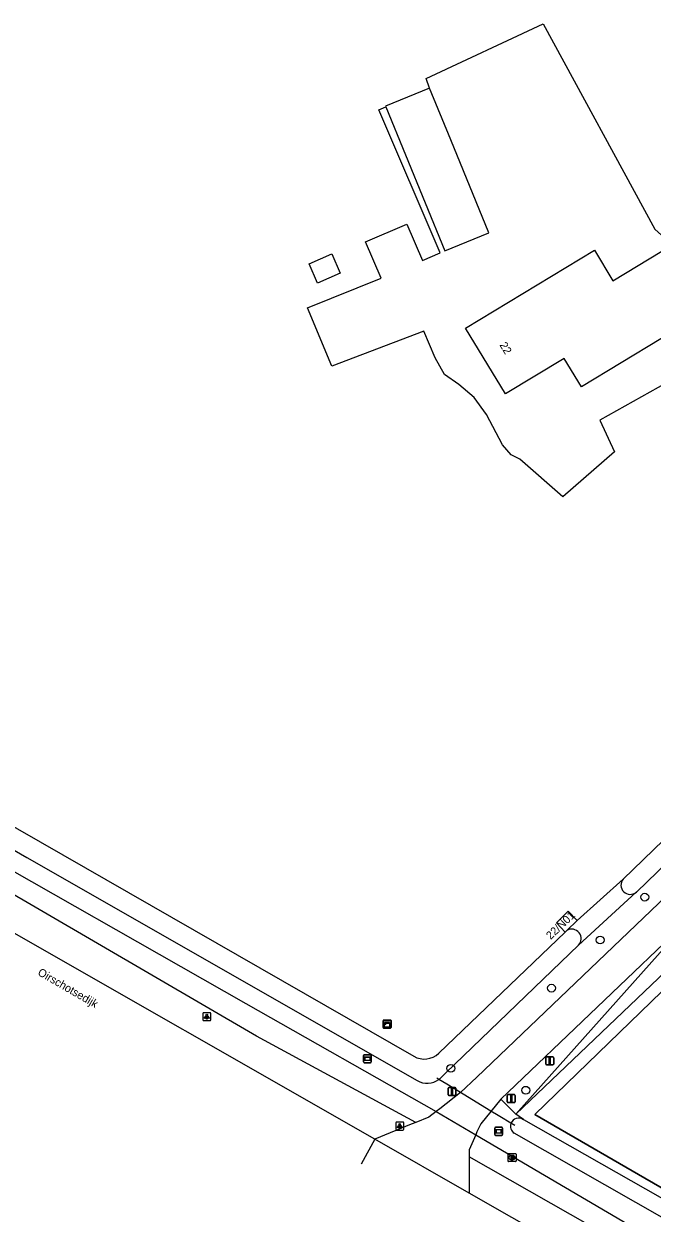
# Model space of a CAD drawing. Extents: x 157154 to 159278, y 385000 to 386650.
# Drawn here: x 157381.9 to 157460.3, y 385928.5 to 386077 of the extents above; entities that cross this region are included whole.
import ezdxf

# ---------------------------------------------------------------- set-up
doc = ezdxf.new("R2010")
doc.units = 0
for name, color, linetype in [('IMGEO_Berm_groen', 7, 'Continuous'), ('IMGEO_Boom', 7, 'Continuous'), ('IMGEO_Brandkraan', 7, 'Continuous'), ('IMGEO_Duiker', 7, 'Continuous'), ('IMGEO_Gemengd_bos', 7, 'Continuous'), ('IMGEO_Groenvoorziening', 7, 'Continuous'), ('IMGEO_Hek', 7, 'Continuous'), ('IMGEO_Kast', 7, 'Continuous'), ('IMGEO_Lichtpunt', 7, 'Continuous'), ('IMGEO_Loofbos', 7, 'Continuous'), ('IMGEO_Openbare_ruimte_label', 7, 'Continuous'), ('IMGEO_Pand', 7, 'Continuous'), ('IMGEO_Pand_nummerreeks', 7, 'Continuous'), ('IMGEO_Rijbaan_lokaal_gesloten', 7, 'Continuous'), ('IMGEO_Rijbaan_lokaal_open', 7, 'Continuous'), ('IMGEO_Verkeersbordpaal', 7, 'Continuous'), ('IMGEO_Verklikker', 7, 'Continuous'), ('IMGEO_Voetpad_open', 7, 'Continuous'), ('IMGEO_Waterloop', 7, 'Continuous')]:
    doc.layers.add(name, color=color, linetype=linetype)

msp = doc.modelspace()

# ---------------------------------------------------------------- linework, layer by layer
at = {"layer": 'IMGEO_Berm_groen'}
for points in [[(157441.44, 385942.69), (157443.32, 385940.84)], [(157444.27, 385940.14), (157443.32, 385940.84)]]:
    msp.add_lwpolyline(points, dxfattribs=at)
at = {"layer": 'IMGEO_Boom'}
for centre in [(157459.42, 385967.94), (157453.84, 385962.58), (157447.77, 385956.57), (157435.2, 385946.55), (157444.56, 385943.81)]:
    msp.add_circle(centre, 0.489, dxfattribs=at)
at = {"layer": 'IMGEO_Brandkraan'}
for p, q in [((157442.34, 385934.97), (157442.34, 385935.83)), ((157442.41, 385935.9), (157443.26, 385935.9)), ((157442.82, 385935.68), (157442.85, 385935.68)), ((157443.34, 385935.83), (157443.34, 385934.97)), ((157443.26, 385934.9), (157442.41, 385934.9)), ((157442.85, 385935.12), (157442.82, 385935.12))]:
    msp.add_line(p, q, dxfattribs=at)
for points in [[(157442.34, 385934.97), (157442.34, 385935.83)], [(157442.41, 385935.9), (157443.26, 385935.9)], [(157443.34, 385935.83), (157443.34, 385934.97)], [(157443.26, 385934.9), (157442.41, 385934.9)], [(157442.68, 385935.6), (157442.68, 385935.2), (157442.9, 385935.2)], [(157442.91, 385935.6), (157442.68, 385935.6)], [(157442.86, 385935.52), (157442.81, 385935.52), (157442.81, 385935.44)], [(157442.81, 385935.44), (157442.86, 385935.44)], [(157442.87, 385935.37), (157442.81, 385935.37), (157442.81, 385935.29)], [(157442.81, 385935.29), (157442.87, 385935.29)]]:
    msp.add_lwpolyline(points, dxfattribs=at)
for centre, radius, start, end in [((157442.41, 385935.82), 0.0765, 91.552, 178.448), ((157442.41, 385935.82), 0.0765, 91.552, 178.448), ((157443.26, 385935.82), 0.0765, 1.552, 88.448), ((157443.26, 385935.82), 0.0765, 1.552, 88.448), ((157442.41, 385934.98), 0.0765, 181.552, 268.448), ((157442.41, 385934.98), 0.0765, 181.552, 268.448), ((157442.86, 385935.48), 0.0379, 267.8285, 90.9355), ((157442.87, 385935.33), 0.0404, 269.8759, 90.5077), ((157442.9, 385935.45), 0.251, 268.6676, 293.5347), ((157442.92, 385935.45), 0.145, 59.4692, 91.5367), ((157442.94, 385935.5), 0.0922, 285.5137, 58.1501), ((157442.95, 385935.31), 0.105, 301.3115, 78.989), ((157443.26, 385934.98), 0.0765, 271.552, 358.448), ((157443.26, 385934.98), 0.0765, 271.552, 358.448)]:
    msp.add_arc(centre, radius, start, end, dxfattribs=at)
for centre, major_axis, ratio, start_param, end_param in [((157442.82, 385935.4), (-0.387, 0.002), 0.722429, 4.712389, 7.853982), ((157442.85, 385935.4), (-0.39, 0.002), 0.717154, 1.570796, 4.712389)]:
    msp.add_ellipse(centre, major_axis=major_axis, ratio=ratio, start_param=start_param, end_param=end_param, dxfattribs=at)
at = {"layer": 'IMGEO_Duiker'}
msp.add_lwpolyline([(157443.18, 385939.39), (157442.7, 385939.68), (157441.3, 385940.54), (157439.99, 385941.34), (157436.4, 385943.52), (157434.69, 385944.57), (157433.71, 385945.17), (157433.47, 385945.31)], dxfattribs=at)
at = {"layer": 'IMGEO_Gemengd_bos'}
for points in [[(157539.91, 385944.1), (157541.98, 385942.04), (157512.6, 385902.07), (157445.67, 385940.77), (157469.45, 385963.81), (157474.9, 385958.09), (157475.08, 385958.27), (157469.44, 385964.19), (157468.14, 385962.94), (157468, 385963.08), (157467.36, 385963.75)], [(157467.36, 385963.75), (157443.32, 385940.84)]]:
    msp.add_lwpolyline(points, dxfattribs=at)
at = {"layer": 'IMGEO_Groenvoorziening'}
for points in [[(157458.36, 385968.55), (157451.13, 385961.92)], [(157443.32, 385940.84), (157465.49, 385965.68)]]:
    msp.add_lwpolyline(points, dxfattribs=at)
at = {"layer": 'IMGEO_Hek'}
msp.add_lwpolyline([(157475.08, 385958.27), (157474.9, 385958.09), (157469.45, 385963.81), (157445.67, 385940.77), (157512.6, 385902.07), (157541.98, 385942.04), (157539.91, 385944.1)], dxfattribs=at)
at = {"layer": 'IMGEO_Kast'}
for p, q in [((157426.74, 385951.65), (157426.74, 385952.5)), ((157426.74, 385952.5), (157426.74, 385951.65)), ((157426.81, 385952.58), (157427.65, 385952.58)), ((157427.65, 385952.58), (157426.81, 385952.58)), ((157427.73, 385952.51), (157427.73, 385951.66)), ((157427.73, 385951.66), (157427.73, 385952.51)), ((157427.66, 385951.58), (157426.82, 385951.58)), ((157426.82, 385951.58), (157427.66, 385951.58))]:
    msp.add_line(p, q, dxfattribs=at)
for points in [[(157426.93, 385952.37), (157427.53, 385952.37), (157427.53, 385952.28), (157426.93, 385952.28), (157426.93, 385952.37)], [(157426.93, 385952.2), (157427.53, 385952.2), (157427.53, 385951.71), (157426.93, 385951.71), (157426.93, 385952.2)]]:
    msp.add_lwpolyline(points, dxfattribs=at)
msp.add_circle((157427.01, 385952.04), 0.0377, dxfattribs=at)
for centre, start, end in [((157426.81, 385952.5), 92.4484, 184.2845), ((157426.81, 385952.5), 92.4484, 184.2845), ((157427.66, 385952.5), 2.4484, 94.2845), ((157427.66, 385952.5), 2.4484, 94.2845), ((157426.81, 385951.66), 182.4484, 274.2845), ((157426.81, 385951.66), 182.4484, 274.2845), ((157427.66, 385951.66), 272.4484, 4.2845), ((157427.66, 385951.66), 272.4484, 4.2845)]:
    msp.add_arc(centre, 0.0779, start, end, dxfattribs=at)
at = {"layer": 'IMGEO_Lichtpunt'}
for p, q in [((157405.13, 385953.5), (157404.32, 385953.5)), ((157405.13, 385953.5), (157404.32, 385953.5)), ((157404.22, 385953.41), (157404.22, 385952.6)), ((157404.22, 385953.41), (157404.22, 385952.6)), ((157404.32, 385952.51), (157405.13, 385952.51)), ((157404.32, 385952.51), (157405.13, 385952.51)), ((157405.22, 385952.6), (157405.22, 385953.41)), ((157405.22, 385952.6), (157405.22, 385953.41)), ((157428.32, 385939.75), (157428.32, 385938.94)), ((157428.32, 385939.75), (157428.32, 385938.94)), ((157429.22, 385939.84), (157428.42, 385939.84)), ((157429.22, 385939.84), (157428.42, 385939.84)), ((157428.42, 385938.84), (157429.22, 385938.84)), ((157428.42, 385938.84), (157429.22, 385938.84)), ((157429.32, 385938.94), (157429.32, 385939.75)), ((157429.32, 385938.94), (157429.32, 385939.75))]:
    msp.add_line(p, q, dxfattribs=at)
for points in [[(157404.6, 385953.07), (157404.64, 385953.05), (157404.45, 385952.78), (157404.41, 385952.81), (157404.6, 385953.07)], [(157404.7, 385953.03), (157404.75, 385953.03), (157404.75, 385952.7), (157404.7, 385952.7), (157404.7, 385953.03)], [(157404.81, 385953.05), (157404.85, 385953.07), (157405.03, 385952.81), (157405, 385952.78), (157404.81, 385953.05)], [(157428.7, 385939.41), (157428.73, 385939.38), (157428.55, 385939.12), (157428.51, 385939.15), (157428.7, 385939.41)], [(157428.8, 385939.36), (157428.84, 385939.36), (157428.84, 385939.04), (157428.8, 385939.04), (157428.8, 385939.36)], [(157428.91, 385939.38), (157428.95, 385939.41), (157429.13, 385939.15), (157429.09, 385939.12), (157428.91, 385939.38)]]:
    msp.add_lwpolyline(points, dxfattribs=at)
for centre in [(157404.72, 385953.21), (157428.82, 385939.54)]:
    msp.add_circle(centre, 0.0994, dxfattribs=at)
for centre, start, end in [((157404.32, 385953.41), 90, 180), ((157404.32, 385953.41), 90, 180), ((157405.13, 385953.41), 0, 90), ((157405.13, 385953.41), 0, 90), ((157404.32, 385952.6), 180, 270), ((157404.32, 385952.6), 180, 270), ((157405.13, 385952.6), 270, 0), ((157405.13, 385952.6), 270, 360), ((157428.42, 385939.75), 90, 180), ((157428.42, 385939.75), 90, 180), ((157428.42, 385938.94), 180, 270), ((157428.42, 385938.94), 180, 270), ((157429.22, 385939.75), 0, 90), ((157429.22, 385939.75), 0, 90), ((157429.22, 385938.94), 270, 0), ((157429.22, 385938.94), 270, 360)]:
    msp.add_arc(centre, 0.0946, start, end, dxfattribs=at)
at = {"layer": 'IMGEO_Loofbos'}
for points in [[(157432.54, 386069), (157432.1, 386070.21), (157446.73, 386077.04), (157460.69, 386051.4), (157464.93, 386047.56), (157471.54, 386036.91), (157471.52, 386035.08)], [(157470.89, 386032.16), (157465.26, 386033.93), (157453.79, 386027.52), (157455.64, 386023.55), (157449.19, 386017.95), (157443.83, 386022.67), (157442.74, 386023.19), (157441.67, 386024.45), (157439.64, 386028.24), (157438.12, 386030.34), (157436.21, 386031.99), (157434.42, 386033.23), (157433.26, 386035.33), (157431.83, 386038.65), (157420.32, 386034.26), (157417.3, 386041.54), (157426.49, 386045.26), (157424.54, 386049.8), (157429.7, 386052.02), (157431.65, 386047.47), (157433.87, 386048.42), (157426.2, 386066.3), (157427.08, 386066.69)], [(157421.39, 386045.87), (157418.53, 386044.65), (157417.49, 386047.07), (157420.35, 386048.29), (157421.39, 386045.87)], [(157450.96, 385965), (157456.7, 385970.18)]]:
    msp.add_lwpolyline(points, dxfattribs=at)
at = {"layer": 'IMGEO_Pand'}
for points in [[(157432.54, 386069), (157427.05, 386066.76), (157427.08, 386066.69)], [(157427.08, 386066.69), (157434.46, 386048.67), (157439.94, 386050.92), (157435.18, 386062.56), (157432.54, 386069)], [(157451.5, 386031.69), (157449.35, 386035.24), (157442.01, 386030.8), (157437.03, 386039.02), (157453.13, 386048.77), (157455.44, 386044.95), (157461.55, 386048.65), (157466.37, 386040.7), (157451.5, 386031.69)], [(157449.48, 385963.58), (157448.38, 385964.74), (157449.86, 385966.17), (157450.96, 385965)], [(157450.96, 385965), (157449.68, 385963.77)], [(157449.68, 385963.77), (157449.48, 385963.58)]]:
    msp.add_lwpolyline(points, dxfattribs=at)
at = {"layer": 'IMGEO_Rijbaan_lokaal_gesloten'}
for points in [[(157425.7, 385937.7), (157378.01, 385964.93), (157301.73, 386008.65), (157245.84, 386040.45)], [(157425.7, 385937.7), (157424, 385934.57)], [(157437.5, 385930.96), (157425.7, 385937.7)], [(157627.36, 385822.87), (157615.19, 385829.67), (157559.47, 385861.36), (157437.5, 385930.96)]]:
    msp.add_lwpolyline(points, dxfattribs=at)
at = {"layer": 'IMGEO_Rijbaan_lokaal_open'}
for points in [[(157516.04, 386019.65), (157438.46, 385945.46), (157436.42, 385943.53), (157433.81, 385941.48), (157433.37, 385941.16)], [(157465.49, 385965.68), (157441.44, 385942.69)], [(157441.44, 385942.69), (157438.94, 385939.63), (157438.46, 385938.6), (157438.31, 385938.26)], [(157433.37, 385941.16), (157432.43, 385940.47), (157430.82, 385939.8)], [(157433.37, 385941.16), (157438.31, 385938.26)], [(157430.82, 385939.8), (157430.25, 385939.57), (157425.7, 385937.7)], [(157438.31, 385938.26), (157437.49, 385936.38), (157437.5, 385935.48)], [(157437.5, 385935.48), (157437.5, 385930.96)]]:
    msp.add_lwpolyline(points, dxfattribs=at)
at = {"layer": 'IMGEO_Verkeersbordpaal'}
for p, q in [((157447.05, 385947.08), (157447.05, 385947.88)), ((157447.05, 385947.88), (157447.05, 385947.08)), ((157447.15, 385947.98), (157447.94, 385947.98)), ((157447.94, 385947.98), (157447.15, 385947.98)), ((157448.04, 385947.88), (157448.04, 385947.08)), ((157448.04, 385947.08), (157448.04, 385947.88)), ((157447.94, 385946.98), (157447.15, 385946.98)), ((157447.15, 385946.98), (157447.94, 385946.98)), ((157434.85, 385943.26), (157434.85, 385944.06)), ((157434.85, 385944.06), (157434.85, 385943.26)), ((157434.95, 385944.16), (157435.74, 385944.16)), ((157435.74, 385944.16), (157434.95, 385944.16)), ((157435.74, 385943.16), (157434.95, 385943.16)), ((157434.95, 385943.16), (157435.74, 385943.16)), ((157435.84, 385944.06), (157435.84, 385943.26)), ((157435.84, 385943.26), (157435.84, 385944.06)), ((157442.25, 385942.37), (157442.25, 385943.17)), ((157442.25, 385943.17), (157442.25, 385942.37)), ((157442.35, 385943.27), (157443.14, 385943.27)), ((157443.14, 385943.27), (157442.35, 385943.27)), ((157443.24, 385943.17), (157443.24, 385942.37)), ((157443.24, 385942.37), (157443.24, 385943.17)), ((157443.14, 385942.27), (157442.35, 385942.27)), ((157442.35, 385942.27), (157443.14, 385942.27))]:
    msp.add_line(p, q, dxfattribs=at)
for points in [[(157447.47, 385947.85), (157447.62, 385947.85), (157447.62, 385947.1), (157447.47, 385947.1), (157447.47, 385947.85)], [(157435.27, 385944.03), (157435.42, 385944.03), (157435.42, 385943.28), (157435.27, 385943.28), (157435.27, 385944.03)], [(157442.67, 385943.15), (157442.82, 385943.15), (157442.82, 385942.4), (157442.67, 385942.4), (157442.67, 385943.15)]]:
    msp.add_lwpolyline(points, dxfattribs=at)
for centre, start, end in [((157447.15, 385947.88), 90, 180), ((157447.15, 385947.88), 90, 180), ((157447.94, 385947.88), 0, 90), ((157447.94, 385947.88), 360, 90), ((157447.15, 385947.08), 180, 270), ((157447.15, 385947.08), 180, 270), ((157447.94, 385947.08), 270, 0), ((157447.94, 385947.08), 270, 0), ((157434.95, 385944.06), 90, 180), ((157434.95, 385944.06), 90, 180), ((157434.95, 385943.26), 180, 270), ((157434.95, 385943.26), 180, 270), ((157435.74, 385944.06), 0, 90), ((157435.74, 385944.06), 360, 90), ((157435.74, 385943.26), 270, 0), ((157435.74, 385943.26), 270, 0), ((157442.35, 385943.17), 90, 180), ((157442.35, 385943.17), 90, 180), ((157443.14, 385943.17), 0, 90), ((157443.14, 385943.17), 360, 90), ((157442.35, 385942.37), 180, 270), ((157442.35, 385942.37), 180, 270), ((157443.14, 385942.37), 270, 0), ((157443.14, 385942.37), 270, 0)]:
    msp.add_arc(centre, 0.1, start, end, dxfattribs=at)
at = {"layer": 'IMGEO_Verklikker'}
for p, q in [((157424.29, 385947.35), (157424.29, 385948.15)), ((157424.29, 385948.15), (157424.29, 385947.35)), ((157424.39, 385948.25), (157425.17, 385948.25)), ((157425.17, 385948.25), (157424.39, 385948.25)), ((157425.27, 385948.15), (157425.27, 385947.35)), ((157425.27, 385947.35), (157425.27, 385948.15)), ((157425.17, 385947.25), (157424.39, 385947.25)), ((157424.39, 385947.25), (157425.17, 385947.25)), ((157440.68, 385938.28), (157440.68, 385939.08)), ((157440.68, 385939.08), (157440.68, 385938.28)), ((157440.78, 385939.18), (157441.57, 385939.18)), ((157441.57, 385939.18), (157440.78, 385939.18)), ((157441.67, 385939.08), (157441.67, 385938.28)), ((157441.67, 385938.28), (157441.67, 385939.08)), ((157441.57, 385938.18), (157440.78, 385938.18)), ((157440.78, 385938.18), (157441.57, 385938.18))]:
    msp.add_line(p, q, dxfattribs=at)
for points in [[(157424.39, 385947.99), (157425.17, 385947.99), (157425.17, 385947.52), (157424.39, 385947.52), (157424.39, 385947.99)], [(157424.45, 385947.92), (157424.45, 385947.59), (157425.11, 385947.59), (157425.11, 385947.92), (157424.45, 385947.92)], [(157440.78, 385938.91), (157441.56, 385938.91), (157441.56, 385938.45), (157440.78, 385938.45), (157440.78, 385938.91)], [(157440.84, 385938.85), (157440.84, 385938.51), (157441.5, 385938.51), (157441.5, 385938.85), (157440.84, 385938.85)]]:
    msp.add_lwpolyline(points, dxfattribs=at)
for centre, start, end in [((157424.39, 385948.15), 90, 180), ((157424.39, 385948.15), 90, 180), ((157425.17, 385948.15), 0, 90), ((157425.17, 385948.15), 360, 90), ((157424.39, 385947.35), 180, 270), ((157424.39, 385947.35), 180, 270), ((157425.17, 385947.35), 270, 0), ((157425.17, 385947.35), 270, 0), ((157440.78, 385939.08), 90, 180), ((157440.78, 385939.08), 90, 180), ((157441.57, 385939.08), 0, 90), ((157441.57, 385939.08), 360, 90), ((157440.78, 385938.28), 180, 270), ((157440.78, 385938.28), 180, 270), ((157441.57, 385938.28), 270, 0), ((157441.57, 385938.28), 270, 0)]:
    msp.add_arc(centre, 0.1, start, end, dxfattribs=at)
at = {"layer": 'IMGEO_Voetpad_open'}
for points in [[(157211.87, 386068.54), (157226.55, 386059.05), (157238.01, 386052.55), (157275.38, 386031.65), (157325.1, 386002.94), (157371.95, 385976.04), (157409.6, 385954.65), (157433.37, 385941.16)], [(157430.82, 385939.8), (157410.95, 385950.56), (157358.1, 385981.34), (157315.93, 386005.59), (157238.95, 386049.87), (157225.52, 386057.6), (157213.47, 386063.29)], [(157438.31, 385938.26), (157463.35, 385923.54), (157510.58, 385896.66), (157634.81, 385826.59)], [(157632.03, 385824.56), (157561.33, 385864.98), (157437.5, 385935.48)]]:
    msp.add_lwpolyline(points, dxfattribs=at)
at = {"layer": 'IMGEO_Waterloop'}
for points in [[(157300.64, 386022.93), (157328.54, 386006.7), (157340.05, 386000), (157430.56, 385948.06)], [(157301.16, 386019.38), (157327.31, 386004.6), (157335.45, 386000), (157382.24, 385972.9), (157430.99, 385945.03)], [(157456.7, 385970.18), (157466.79, 385979.94)], [(157458.36, 385968.55), (157458.4, 385968.59), (157458.43, 385968.62), (157468.65, 385978.5)], [(157433.68, 385948.44), (157449.48, 385963.58)], [(157433.99, 385945.4), (157434.59, 385945.98), (157451.13, 385961.92)], [(157444.27, 385940.14), (157500, 385908.46), (157548.85, 385880.7), (157597.28, 385853.18), (157604.81, 385848.82)], [(157603.52, 385846.95), (157547.72, 385878.78), (157500, 385906), (157443.12, 385938.45)]]:
    msp.add_lwpolyline(points, dxfattribs=at)
for centre, radius, start, end in [((157457.61, 385969.45), 1.17, 141.1503, 310.0361), ((157450.28, 385962.75), 1.19, 315.7058, 120.7398), ((157431.87, 385950.32), 2.61, 240.0816, 313.8649), ((157432.24, 385947.21), 2.52, 240.2575, 305.726), ((157432.26, 385947.19), 2.49, 305.5707, 314.0404), ((157443.66, 385939.31), 1.02, 53.4832, 158.8821), ((157443.66, 385939.31), 1.02, 158.9445, 238.1756)]:
    msp.add_arc(centre, radius, start, end, dxfattribs=at)

# ---------------------------------------------------------------- texts
at = {"layer": 'IMGEO_Openbare_ruimte_label'}
msp.add_text('Oirschotsedijk', height=1, rotation=329.8714, dxfattribs=at).set_placement((157383.52, 385958.27))
at = {"layer": 'IMGEO_Pand_nummerreeks'}
for s, rotation, p in [('22', 301.1989, (157441.24, 386036.92)), ('22/N01', 43.3801, (157447.66, 385962.58))]:
    msp.add_text(s, height=1, rotation=rotation, dxfattribs=at).set_placement(p)

doc.saveas('drawing.dxf')
